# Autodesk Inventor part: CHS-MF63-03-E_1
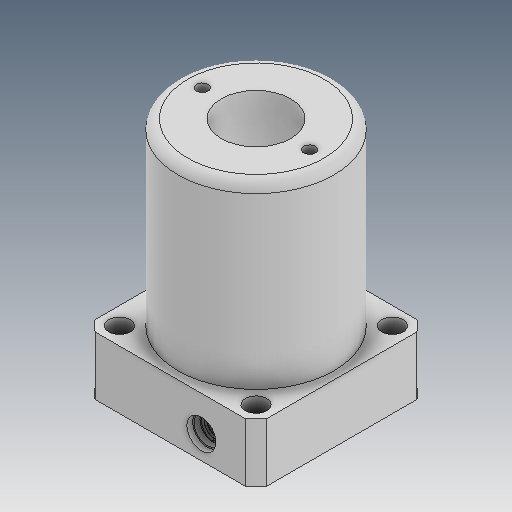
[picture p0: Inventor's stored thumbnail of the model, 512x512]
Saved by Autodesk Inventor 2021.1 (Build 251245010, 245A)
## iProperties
Created: 2019-05
Part Number: CHS-MF63-03-E_1
Material: Ogólny
Document SubType Name: Modeling
Designer: user
Density: 1 g/cm^3
Appearance: Domyślna
Author: user
Revision Number: ÈÎºÎ
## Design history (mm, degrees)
feature "ÊäÈë1"
node "Bryła1"
